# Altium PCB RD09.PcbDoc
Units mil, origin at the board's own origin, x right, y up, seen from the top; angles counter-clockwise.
Board outline 1064.96 x 551.18 mil, 4 copper layers (Top Layer, Mid Layer 1, Mid Layer 2, Bottom Layer), stack 56.756 mil thick; 39 components, 35 nets, 118 pads, 211 vias.
Unrouted connection lines stored in the file: 34.
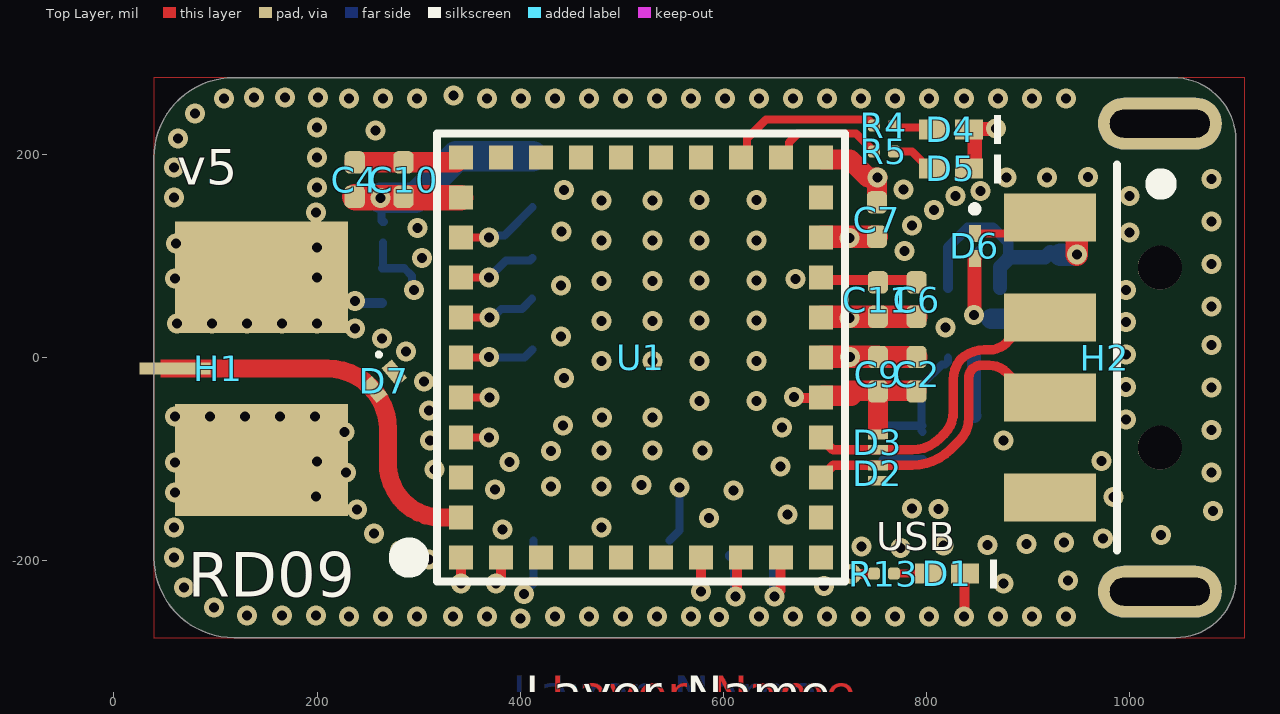
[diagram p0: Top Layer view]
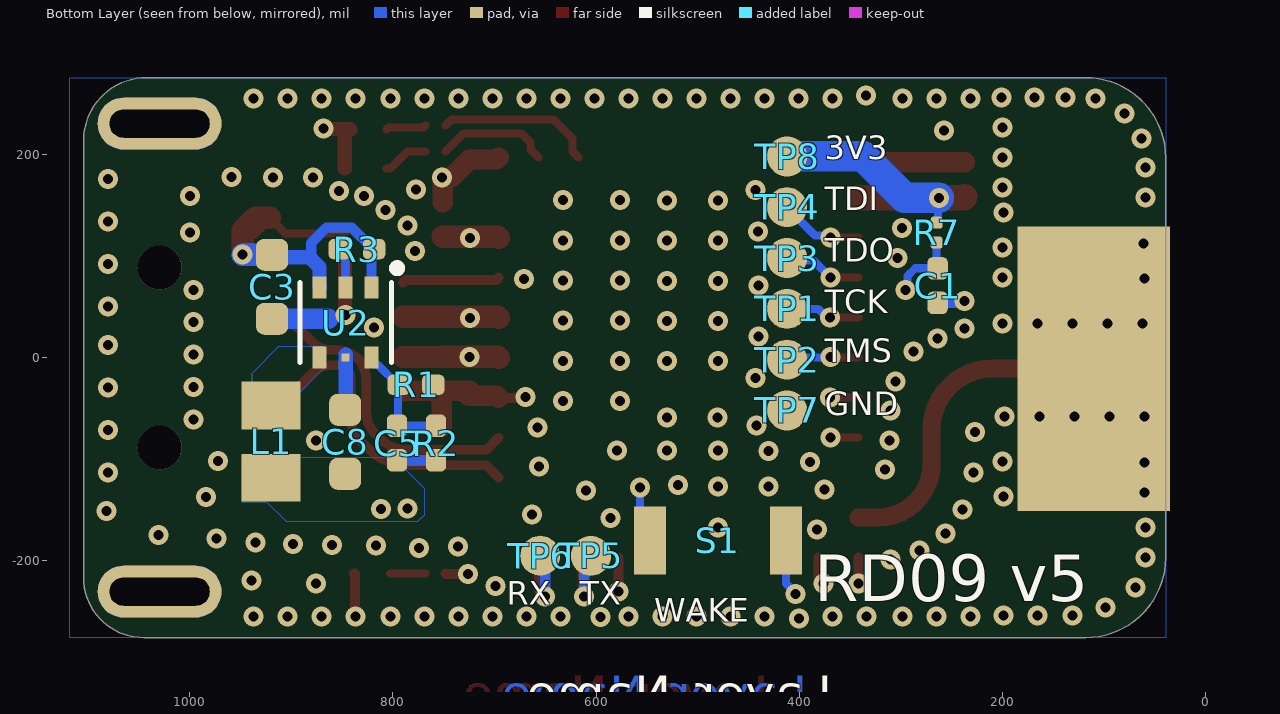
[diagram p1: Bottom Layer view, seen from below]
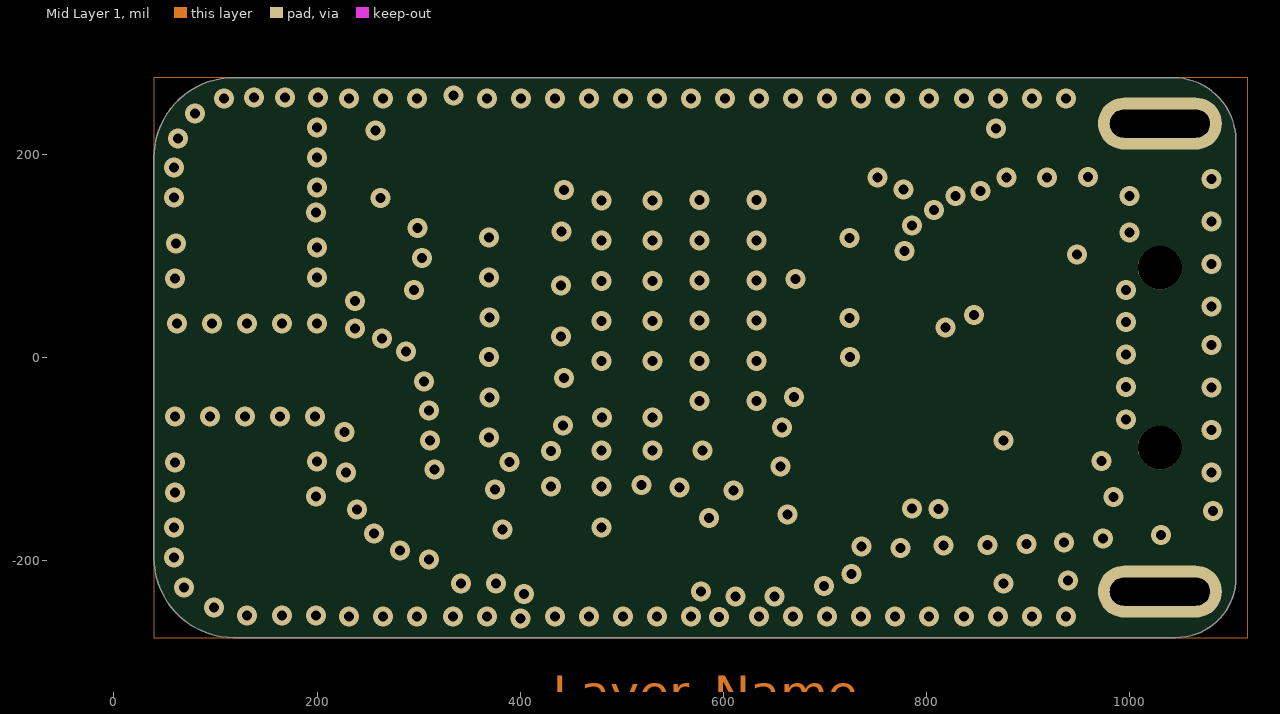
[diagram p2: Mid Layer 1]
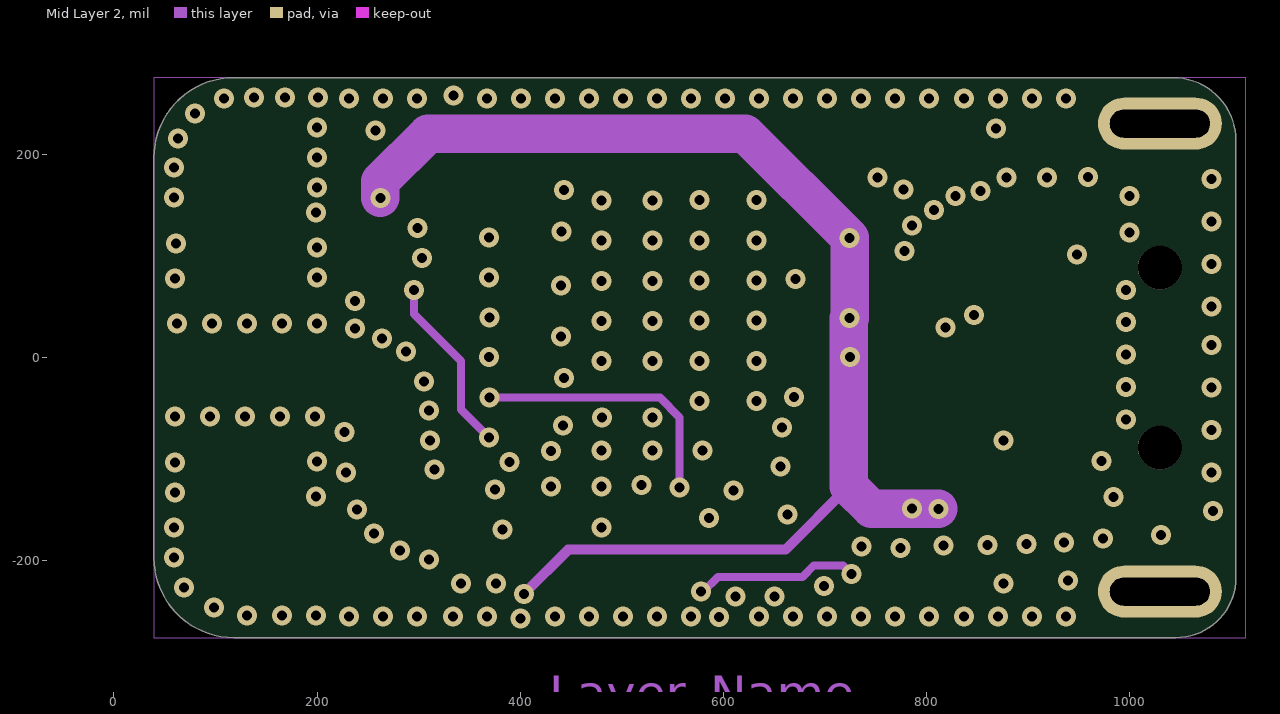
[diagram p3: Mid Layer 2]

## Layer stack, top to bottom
Top Solder: solder mask 0.787, SM-001, Dk 4.2
Top Layer: signal copper 1.378
Dielectric 1: prepreg 12, PP, Dk 4.29
Mid Layer 1: signal copper 1.378
Dielectric 2: core 27.2441, Core, Dk 4.29
Mid Layer 2: signal copper 1.378
Dielectric 3: prepreg 12, PP, Dk 4.29
Bottom Layer: signal copper 1.378
Bottom Solder: solder mask 0.787, SM-001, Dk 4.2

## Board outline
39.37,-196.85 39.37,196.85 cw(c118.11,196.85) 118.11,275.59 1042.32,275.59 cw(c1042.32,213.58) 1104.33,213.58 1104.33,-216.54 cw(c1045.28,-216.54) 1045.28,-275.59 118.11,-275.59 cw(c118.11,-196.85)

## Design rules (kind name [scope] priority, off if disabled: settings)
AssemblyTestPointUsage [All] p0: scope1count=1 scope1_0_kind=Board scope1_0_value=Board scope2count=1 scope2_0_kind=Board scope2_0_value=Board commentlength=0
AssemblyTestpoint [All] p0: scope1count=1 scope1_0_kind=Board scope1_0_value=Board scope2count=1 scope2_0_kind=Board scope2_0_value=Board commentlength=0
BoardOutlineClearance [All] p0: scope1count=1 scope1_0_kind=Board scope1_0_value=Board scope2count=1 scope2_0_kind=Board scope2_0_value=Board commentlength=0 gap=6
BoardOutlineClearance [All] p1: gap=6 ignorepadtopadclearanceinfootprint=FALSE
Clearance [All] p0 off: scope1count=1 scope1_0_kind=Board scope1_0_value=Board scope2count=1 scope2_0_kind=Board scope2_0_value=Board commentlength=69 gap=5 // Protel DXP Scope 2 Expression Was: Not(OnLayer('Keep-Out Layer'))
Clearance "Poly Clearance" [All] p0 off: scope1count=1 scope1_0_kind=Board scope1_0_value=Board scope2count=1 scope2_0_kind=Board scope2_0_value=Board commentlength=50 gap=4 // Protel DXP Scope 1 Expression Was: (InPolygon)
Clearance "Poly Clearance_USB" [All] p0 off: scope1count=1 scope1_0_kind=Board scope1_0_value=Board scope2count=1 scope2_0_kind=Board scope2_0_value=Board commentlength=50 gap=5.74 // Protel DXP Scope 2 Expression Was: (InPolygon)
Clearance Clearance_RF [All] p0 off: scope1count=1 scope1_0_kind=Board scope1_0_value=Board scope2count=1 scope2_0_kind=Board scope2_0_value=Board commentlength=50 gap=11.81 // Protel DXP Scope 2 Expression Was: (InPolygon)
Clearance Clearance_keepout [All] p0 off: scope1count=1 scope1_0_kind=Layer scope1_0_value=TOP scope2count=1 scope2_0_kind=Board scope2_0_value=Board commentlength=50 gap=6 // Protel DXP Scope 2 Expression Was: (InPolygon)
Clearance Clearance_RFVia [All] p0 off: scope1count=1 scope1_0_kind=Board scope1_0_value=Board scope2count=1 scope2_0_kind=Board scope2_0_value=Board commentlength=71 gap=7 // Protel DXP Scope 1 Expression Was: (IsVia AND InNetClass('RF-Net'))
Clearance Clearance_RFVia [(IsVia AND InNetClass('RF-Net'))] p1: gap=7 ignorepadtopadclearanceinfootprint=FALSE
Clearance Clearance_keepout [OnLayer('Keep-Out Layer') vs (InPolygon)] p2: gap=6 ignorepadtopadclearanceinfootprint=FALSE except(0: Arc-Hole Track-Hole SMDPad-Hole THPad-Hole Via-Hole Fill-Hole Poly-Hole Region-Hole Text-Hole)
Clearance Clearance_RF [InNetClass('RF-Net') and ( IsArc or IsTrack ) vs (InPolygon)] p3: gap=11.81 ignorepadtopadclearanceinfootprint=FALSE
Clearance "Poly Clearance_USB" [InNet('USB_D_N') or InNet('USB_D_P') vs (InPolygon)] p4: gap=5.74 ignorepadtopadclearanceinfootprint=FALSE
Clearance "Poly Clearance" [(InPolygon)] p5: gap=4 ignorepadtopadclearanceinfootprint=FALSE except(0: Arc-Hole Track-Hole SMDPad-Hole THPad-Hole Via-Hole Fill-Hole Poly-Hole Region-Hole Text-Hole)
Clearance [Not(OnLayer('Keep-Out Layer')) vs Not(OnLayer('Keep-Out Layer'))] p6: gap=5 ignorepadtopadclearanceinfootprint=FALSE
ComponentClearance COMP_OTHER-COMP_OTHER [All] p0: scope1count=1 scope1_0_kind=ComponentClass scope1_0_value=COMP_OTHER scope2count=1 scope2_0_kind=ComponentClass scope2_0_value=COMP_OTHER commentlength=0 gap=14.96 collisioncheckmode=3
ComponentClearance CHIP_MICRO-COMP_OTHER [All] p0: scope1count=1 scope1_0_kind=ComponentClass scope1_0_value=CHIP_MICRO scope2count=1 scope2_0_kind=ComponentClass scope2_0_value=COMP_OTHER commentlength=0 gap=11.81 collisioncheckmode=3
ComponentClearance COMP_BGA-COMP_OTHER [All] p0: scope1count=1 scope1_0_kind=ComponentClass scope1_0_value=COMP_BGA scope2count=1 scope2_0_kind=ComponentClass scope2_0_value=COMP_OTHER commentlength=0 gap=23.62 collisioncheckmode=3
ComponentClearance COMP_BGA-COMP_BGA [All] p0: scope1count=1 scope1_0_kind=ComponentClass scope1_0_value=COMP_BGA scope2count=1 scope2_0_kind=ComponentClass scope2_0_value=COMP_BGA commentlength=0 gap=39.37 collisioncheckmode=3
ComponentClearance CHIP_MICRO-COMP_BGA [All] p0: scope1count=1 scope1_0_kind=ComponentClass scope1_0_value=CHIP_MICRO scope2count=1 scope2_0_kind=ComponentClass scope2_0_value=COMP_BGA commentlength=0 gap=11.81 collisioncheckmode=3
ComponentClearance CHIP_OTHER-COMP_OTHER [All] p0: scope1count=1 scope1_0_kind=ComponentClass scope1_0_value=CHIP_OTHER scope2count=1 scope2_0_kind=ComponentClass scope2_0_value=COMP_OTHER commentlength=0 gap=14.96 collisioncheckmode=3
ComponentClearance CHIP_OTHER-COMP_BGA [All] p0: scope1count=1 scope1_0_kind=ComponentClass scope1_0_value=CHIP_OTHER scope2count=1 scope2_0_kind=ComponentClass scope2_0_value=COMP_BGA commentlength=0 gap=14.96 collisioncheckmode=3
ComponentClearance CHIP_OTHER-CHIP_OTHER [All] p0: scope1count=1 scope1_0_kind=ComponentClass scope1_0_value=CHIP_OTHER scope2count=1 scope2_0_kind=ComponentClass scope2_0_value=CHIP_OTHER commentlength=0 gap=9.84 collisioncheckmode=3
ComponentClearance CHIP_MICRO-CHIP_OTHER [All] p0: scope1count=1 scope1_0_kind=ComponentClass scope1_0_value=CHIP_MICRO scope2count=1 scope2_0_kind=ComponentClass scope2_0_value=CHIP_OTHER commentlength=0 gap=9.84 collisioncheckmode=3
ComponentClearance CHIP_MICRO-CHIP_MICRO [All] p0: scope1count=1 scope1_0_kind=ComponentClass scope1_0_value=CHIP_MICRO scope2count=1 scope2_0_kind=ComponentClass scope2_0_value=CHIP_MICRO commentlength=0 gap=7.87 collisioncheckmode=3
ComponentClearance [All] p0: scope1count=1 scope1_0_kind=Component scope1_0_value=SHIELD scope2count=1 scope2_0_kind=Board scope2_0_value=Board commentlength=0 gap=11.81 collisioncheckmode=3
ComponentClearance [InComponent('SHIELD')] p1: gap=11.81 collisioncheckmode=3 verticalgap=10 showdistances=FALSE
ComponentClearance CHIP_MICRO-CHIP_MICRO [InComponentClass('CHIP_MICRO') vs InComponentClass('CHIP_MICRO')] p2: gap=7.87 collisioncheckmode=3 verticalgap=3.94 showdistances=TRUE
ComponentClearance CHIP_MICRO-CHIP_OTHER [InComponentClass('CHIP_MICRO') vs InComponentClass('CHIP_OTHER')] p3: gap=9.84 collisioncheckmode=3 verticalgap=3.94 showdistances=TRUE
ComponentClearance CHIP_OTHER-CHIP_OTHER [InComponentClass('CHIP_OTHER') vs InComponentClass('CHIP_OTHER')] p4: gap=9.84 collisioncheckmode=3 verticalgap=3.94 showdistances=TRUE
ComponentClearance CHIP_OTHER-COMP_BGA [InComponentClass('CHIP_OTHER') vs InComponentClass('COMP_BGA')] p5: gap=14.96 collisioncheckmode=3 verticalgap=3.94 showdistances=TRUE
ComponentClearance CHIP_OTHER-COMP_OTHER [InComponentClass('CHIP_OTHER') vs InComponentClass('COMP_OTHER')] p6: gap=14.96 collisioncheckmode=3 verticalgap=3.94 showdistances=TRUE
ComponentClearance CHIP_MICRO-COMP_BGA [InComponentClass('CHIP_MICRO') vs InComponentClass('COMP_BGA')] p7: gap=11.81 collisioncheckmode=3 verticalgap=3.94 showdistances=TRUE
ComponentClearance COMP_BGA-COMP_BGA [InComponentClass('COMP_BGA') vs InComponentClass('COMP_BGA')] p8: gap=39.37 collisioncheckmode=3 verticalgap=3.94 showdistances=TRUE
ComponentClearance COMP_BGA-COMP_OTHER [InComponentClass('COMP_BGA') vs InComponentClass('COMP_OTHER')] p9: gap=23.62 collisioncheckmode=3 verticalgap=3.94 showdistances=TRUE
ComponentClearance CHIP_MICRO-COMP_OTHER [InComponentClass('CHIP_MICRO') vs InComponentClass('COMP_OTHER')] p10: gap=11.81 collisioncheckmode=3 verticalgap=3.94 showdistances=TRUE
ComponentClearance COMP_OTHER-COMP_OTHER [InComponentClass('COMP_OTHER') vs InComponentClass('COMP_OTHER')] p11: gap=14.96 collisioncheckmode=3 verticalgap=3.94 showdistances=TRUE
DiffPairsRouting [All] p0: scope1count=1 scope1_0_kind=Board scope1_0_value=Board scope2count=1 scope2_0_kind=Board scope2_0_value=Board commentlength=0
DiffPairsRouting [All] p1: maxlimit=10 minlimit=5 mostfreqgap=10 toplayer_mingap=5.74 toplayer_maxgap=5.74 toplayer_prefgap=5.74 toplayer_minwidth=9.45 toplayer_maxwidth=9.45 toplayer_prefwidth=9.45 impedanceprofiledriven=TRUE impedanceprofileid={6CDD10DD-8A0B-4EE0-BC50-81CF0CD2B6CE} impedanceprofilevalue=90.000000 maxuncoupledlength=500
FabricationTestPointUsage TestPointUsage [All] p0: scope1count=1 scope1_0_kind=Board scope1_0_value=Board scope2count=1 scope2_0_kind=Board scope2_0_value=Board commentlength=0 valid=0 allowmultiple=FALSE
FabricationTestPointUsage TestPointUsage [All] p1: valid=0 allowmultiple=FALSE
FabricationTestpoint Testpoint [All] p0: scope1count=1 scope1_0_kind=Board scope1_0_value=Board scope2count=1 scope2_0_kind=Board scope2_0_value=Board commentlength=0 side=3 testpointundercomponent=TRUE minsize=40 maxsize=100 preferedsize=60 minholesize=0 maxholesize=40 preferedholesize=32 testpointgrid=1
FabricationTestpoint Testpoint [All] p1: side=3 testpointundercomponent=TRUE minsize=40 maxsize=100 preferedsize=60 minholesize=0 maxholesize=40 preferedholesize=32 testpointgrid=1 allowsidetop=TRUE allowsidebottom=TRUE usegrid=TRUE gridtolerance=0.01
FanoutControl Fanout_Default [All] p0: scope1count=1 scope1_0_kind=Board scope1_0_value=Board scope2count=1 scope2_0_kind=Board scope2_0_value=Board commentlength=30 // Fanout_Default (Default Rule)
FanoutControl Fanout_Small [All] p0 off: scope1count=1 scope1_0_kind=Board scope1_0_value=Board scope2count=1 scope2_0_kind=Board scope2_0_value=Board commentlength=84 // Protel DXP Scope 1 Expression Was: (CompPinCount < 5)   Fanout_Small (Default Rule)
FanoutControl Fanout_SOIC [All] p0 off: scope1count=1 scope1_0_kind=Board scope1_0_value=Board scope2count=1 scope2_0_kind=Board scope2_0_value=Board commentlength=71 // Protel DXP Scope 1 Expression Was: IsSOIC   Fanout_SOIC (Default Rule)
FanoutControl Fanout_LCC [All] p0 off: scope1count=1 scope1_0_kind=Board scope1_0_value=Board scope2count=1 scope2_0_kind=Board scope2_0_value=Board commentlength=69 // Protel DXP Scope 1 Expression Was: IsLCC   Fanout_LCC (Default Rule)
FanoutControl Fanout_BGA [All] p0 off: scope1count=1 scope1_0_kind=Board scope1_0_value=Board scope2count=1 scope2_0_kind=Board scope2_0_value=Board commentlength=69 // Protel DXP Scope 1 Expression Was: IsBGA   Fanout_BGA (Default Rule)
Height [All] p0: scope1count=1 scope1_0_kind=Board scope1_0_value=Board scope2count=1 scope2_0_kind=Board scope2_0_value=Board commentlength=0
HoleSize [All] p0 off: scope1count=1 scope1_0_kind=Board scope1_0_value=Board scope2count=1 scope2_0_kind=Board scope2_0_value=Board commentlength=0 absolutevalues=TRUE maxlimit=100 minlimit=5.91 maxpercent=80.000 minpercent=20.000
HoleSize [All] p1 off: absolutevalues=TRUE maxlimit=100 minlimit=5.91 maxpercent=80.000 minpercent=20.000
HoleToHoleClearance [All] p0: scope1count=1 scope1_0_kind=Board scope1_0_value=Board scope2count=1 scope2_0_kind=Board scope2_0_value=Board commentlength=0
HoleToHoleClearance [All] p1: gap=8 allowstackedmicrovias=TRUE
LayerPairs [All] p0: scope1count=1 scope1_0_kind=Board scope1_0_value=Board scope2count=1 scope2_0_kind=Board scope2_0_value=Board commentlength=0 enforce=TRUE
MaxMinImpedance [All] p0: scope1count=1 scope1_0_kind=Board scope1_0_value=Board scope2count=1 scope2_0_kind=Board scope2_0_value=Board commentlength=0 minimum=1.000 maximum=10.00
MaxMinImpedance [All] p1: minimum=1.000 maximum=10.00
MinimumAnnularRing [All] p0: scope1count=1 scope1_0_kind=Board scope1_0_value=Board scope2count=1 scope2_0_kind=Board scope2_0_value=Board commentlength=0 minimumring=2.52
MinimumAnnularRing [All] p1: minimumring=2.52
MinimumSolderMaskSliver [All] p0: scope1count=1 scope1_0_kind=Board scope1_0_value=Board scope2count=1 scope2_0_kind=Board scope2_0_value=Board commentlength=0
MinimumSolderMaskSliver [All] p1: minsoldermaskwidth=5
NetAntennae [All] p0: scope1count=1 scope1_0_kind=Board scope1_0_value=Board scope2count=1 scope2_0_kind=Board scope2_0_value=Board commentlength=0
PasteMaskExpansion [All] p0: scope1count=1 scope1_0_kind=Board scope1_0_value=Board scope2count=1 scope2_0_kind=Board scope2_0_value=Board commentlength=0 expansion=0
PlaneClearance [All] p0: scope1count=1 scope1_0_kind=Board scope1_0_value=Board scope2count=1 scope2_0_kind=Board scope2_0_value=Board commentlength=0 clearance=5
PlaneClearance [All] p1: clearance=5
PlaneConnect [All] p0: scope1count=1 scope1_0_kind=Board scope1_0_value=Board scope2count=1 scope2_0_kind=Board scope2_0_value=Board commentlength=0 planeconnectstyle=Direct reliefexpansion=19.68 reliefentries=4 reliefconductorwidth=7.87 reliefairgap=7.87
PlaneConnect [All] p1: planeconnectstyle=Direct reliefexpansion=19.68 reliefentries=4 reliefconductorwidth=7.87 reliefairgap=7.87
PolygonConnect [All] p0: scope1count=1 scope1_0_kind=Board scope1_0_value=Board scope2count=1 scope2_0_kind=Board scope2_0_value=Board commentlength=0 connectstyle=Relief reliefconductorwidth=10 reliefentries=4 polygonreliefangle="90 Angle"
PolygonConnect [All] p1: thpad.connectstyle=Relief thpad.reliefconductorwidth=10 thpad.reliefentries=4 thpad.polygonreliefangle="90 Angle" thpad.airgapwidth=10 smdpad.connectstyle=Direct smdpad.reliefconductorwidth=10 smdpad.reliefentries=4 smdpad.polygonreliefangle="90 Angle" smdpad.airgapwidth=10 via.connectstyle=Direct via.reliefconductorwidth=10 via.reliefentries=4 via.polygonreliefangle="90 Angle" via.airgapwidth=10
RoutingCorners [All] p0: scope1count=1 scope1_0_kind=Board scope1_0_value=Board scope2count=1 scope2_0_kind=Board scope2_0_value=Board commentlength=0 cornerstyle=45-Degree minsetback=100 maxsetback=100
RoutingLayers [All] p0: scope1count=1 scope1_0_kind=Board scope1_0_value=Board scope2count=1 scope2_0_kind=Board scope2_0_value=Board commentlength=0 top layer=Automatic mid layer 1=Automatic mid layer 3=Automatic bottom layer=Automatic
RoutingPriority [All] p0: scope1count=1 scope1_0_kind=Board scope1_0_value=Board scope2count=1 scope2_0_kind=Board scope2_0_value=Board commentlength=0
RoutingTopology [All] p0: scope1count=1 scope1_0_kind=Board scope1_0_value=Board scope2count=1 scope2_0_kind=Board scope2_0_value=Board commentlength=0 topology=Shortest
RoutingVias [All] p0 off: scope1count=1 scope1_0_kind=Board scope1_0_value=Board scope2count=1 scope2_0_kind=Board scope2_0_value=Board commentlength=98 holewidth=7.87 width=19.68 viastyle="Through Hole" minholewidth=7.87 minwidth=17.72 maxholewidth=39.37 maxwidth=78.74 // Protel DXP Scope 1 Expression Was: (StartLayer = 'Top Layer') and (StopLayer = 'Bottom Layer')
RoutingVias [(StartLayer = 'Top Layer') and (StopLayer = 'Bottom Layer')] p1: holewidth=7.87 width=19.68 viastyle="Through Hole" minholewidth=7.87 minwidth=17.72 maxholewidth=39.37 maxwidth=78.74 useviatemplates=TRUE viatemplateguid#1={677E590D-0BF1-4610-8777-1DBFB77D696D} viatemplateguid#2={CDA64F6E-BB79-405B-BF2A-9310D52A7923} viatemplatename#1=v50h25m0mx0 viatemplatename#2=v30h15m0mx0(1)
ShortCircuit [All] p0: scope1count=1 scope1_0_kind=Board scope1_0_value=Board scope2count=1 scope2_0_kind=Board scope2_0_value=Board commentlength=0 allowed=FALSE
SilkToBoardRegionClearance [All] p0: scope1count=1 scope1_0_kind=Board scope1_0_value=Board scope2count=1 scope2_0_kind=Board scope2_0_value=Board commentlength=0
SilkToSilkClearance [All] p0: scope1count=1 scope1_0_kind=Board scope1_0_value=Board scope2count=1 scope2_0_kind=Board scope2_0_value=Board commentlength=0
SilkToSolderMaskClearance SilkscreenOverComponentPads [All] p0 off: scope1count=1 scope1_0_kind=Board scope1_0_value=Board scope2count=1 scope2_0_kind=Board scope2_0_value=Board commentlength=44 // Protel DXP Scope 1 Expression Was: IsPad
SilkToSolderMaskClearance SilkscreenOverComponentPads [IsPad] p1: minsilkscreentomaskgap=7.7 clearancetoexposedcopper=TRUE
SolderMaskExpansion [All] p0: scope1count=1 scope1_0_kind=Board scope1_0_value=Board scope2count=1 scope2_0_kind=Board scope2_0_value=Board commentlength=0 expansion=4
SolderMaskExpansion [All] p1: expansion=4 istentingtop=FALSE
SupplyNets "Schematic Supply Nets_2" [All] p0: scope1count=1 scope1_0_kind=Net scope1_0_value=VDD_3V3 scope2count=1 scope2_0_kind=Board scope2_0_value=Board commentlength=0 voltage=0.000
SupplyNets "Schematic Supply Nets_1" [All] p0: scope1count=1 scope1_0_kind=Net scope1_0_value=GND scope2count=1 scope2_0_kind=Board scope2_0_value=Board commentlength=0 voltage=0.000
SupplyNets "Schematic Supply Nets" [All] p0: scope1count=1 scope1_0_kind=Net scope1_0_value=5V_USB scope2count=1 scope2_0_kind=Board scope2_0_value=Board commentlength=0 voltage=0.000
SupplyNets "Schematic Supply Nets_2" [InNet('VDD_3V3')] p1: voltage=0.000
SupplyNets "Schematic Supply Nets_1" [InNet('GND')] p2: voltage=0.000
SupplyNets "Schematic Supply Nets" [InNet('5V_USB')] p3: voltage=0.000
UnRoutedNet [All] p0: scope1count=1 scope1_0_kind=Board scope1_0_value=Board scope2count=1 scope2_0_kind=Board scope2_0_value=Board commentlength=0
UnpouredPolygon [All] p0: scope1count=1 scope1_0_kind=Board scope1_0_value=Board scope2count=1 scope2_0_kind=Board scope2_0_value=Board commentlength=0
Width [All] p0: scope1count=1 scope1_0_kind=Board scope1_0_value=Board scope2count=1 scope2_0_kind=Board scope2_0_value=Board commentlength=0 maxlimit=100 minlimit=5 preferedwidth=8
Width "RF Net width" [All] p0 off: scope1count=1 scope1_0_kind=Board scope1_0_value=Board scope2count=1 scope2_0_kind=Board scope2_0_value=Board commentlength=61 maxlimit=20 minlimit=3.95 preferedwidth=19.85 // Protel DXP Scope 1 Expression Was: (InNetClass('RF-Net'))
Width "RF Net width" [(InNetClass('RF-Net'))] p1: maxlimit=20 minlimit=3.95 preferedwidth=19.85 toplayer_minwidth=7 toplayer_prefwidth=17.87 impedanceprofiledriven=TRUE impedanceprofileid={2BAD1660-FF1E-4629-AB45-93BC2CD73358} impedanceprofilevalue=50.000000 minimp=50.000000 maximp=50.000000 favimp=50.000000
Width [All] p2: maxlimit=100 minlimit=5 preferedwidth=8 minimp=50.000000 maximp=50.000000 favimp=50.000000
20 further rules are at their usual default settings.

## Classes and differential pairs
component class PCB_PATTERN: TP1 TP2 TP3 TP4 TP5 TP6 TP7 TP8
net class RF-Net: NetD7_2
component class CHIP_OTHER: C3 C8 D1 D4 D5 L1
component class CHIP_MICRO: C1 C2 C4 C5 C6 C7 C9 C10 C11 D6 R1 R3 R4 R5 R7 R13
component class COMP_OTHER: H1 H2 S1 U1 U2
differential pair " ": +USB_D_P -USB_D_N

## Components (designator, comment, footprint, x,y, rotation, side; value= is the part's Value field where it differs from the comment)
C1 "GRM155R61E225ME15D" 0402_cap_rnd#1 263.78,70.9 r270 bottom
C2 "CL05A106MP5NUNC" 0402_cap_rnd#1 790,-16.41 r270 top
C3 "GRM188R61E106MA73J" 0603_cap_rnd 918.79,69.72 r270 bottom
C4 "CL05A106MP5NUNC" 0402_cap_rnd#1 237.01,175.2 r90 top
C5 "CGA2B2NP01H220J050BA" 0402_cap 795.84,-84.07 r90 bottom
C6 "CL05A106MP5NUNC" 0402_cap_rnd#1 790,57.09 r90 top
C7 "C0402C104K8RACTU" 0402_cap_rnd#2 750.98,135.83 r90 top
C8 "GRM188R61E106MA73J" 0603_cap_rnd 846.83,-82.82 r90 bottom
C9 "C0402C104K8RACTU" 0402_cap_rnd#2 751.97,-16.41 r270 top
C10 "C0402C104K8RACTU" 0402_cap_rnd#2 285.04,175.2 r90 top
C11 "C0402C104K8RACTU" 0402_cap_rnd#2 751.97,57.09 r90 top
D1 "XZVGR68W-3" LED_0402_GREEN 820.21,-212.6 r0 top
D2 "SP3522-01UTG" SP3522-01ETG-Footprint-1 751.97,-113.69 r180 top
D3 "SP3522-01UTG" SP3522-01ETG-Footprint-1 751.97,-83.13 r0 top
D4 "LED_R" LED_0402_RED 823.82,224.41 r0 top
D5 "LED_G" LED_0402_GREEN 823.82,186.02 r0 top
D6 "ESDALC6V1-1U2" 0201_DIODE 847.34,109.95 r270 top
D7 "ESD103B102ELE6327XTMA1" INF-TSLP-2-20_V 266.09,-23.32 r310 top
H1 "142-0761-861" SMA_EMERSON_142_0761_861 35.16,-10.83 r90 top locked
H2 "USBA" USBA_BOARD_INLINE 1029.53,0 r90 top locked
L1 "LQM21PN2R2MGHL" INDC2112X06N 919.88,-82.8 r270 bottom
R1 "RC0402FR-07100KL" 0402_res_rnd 777.09,-26.72 r180 bottom
R2 "CRCW0402453KFKEDC" 0402_res 757.51,-84.07 r90 bottom
R3 "RC0402FR-07100KL" 0402_res_rnd 835.39,106.78 r0 bottom
R4 "RES" 0201_res_rnd 757.87,228.35 r0 top
R5 "RES" 0201_res_rnd 757.87,202.76 r0 top
R7 "RC0201FR-07220KL" 0201_res_rnd 264.76,123 r90 bottom
R13 "RC0201FR-07330RL" 0201_res_rnd 757.87,-212.6 r0 top
S1 "B3U-1000P" B3U-1000P 480,-180 r180 bottom
TP1 "PAD0035" TP_40_SMT#1 392.72,38.39 r90 bottom
TP2 "PAD0035" TP_40_SMT#2 392.72,0 r90 bottom
TP3 "PAD0035" TP_40_SMT#3 392.72,78.74 r90 bottom
TP4 "PAD0035" TP_40_SMT#4 392.72,118.11 r90 bottom
TP5 "PAD0035" TP_40_SMT#5 605,-195.04 r90 bottom
TP6 "PAD0035" TP_40_SMT#5 655,-195 r90 bottom
TP7 "PAD0035" TP_40_SMT#6 1178.07,-206.93 r90 bottom
TP8 "PAD0035" TP_40_SMT#7 1408.39,-206.93 r90 bottom
U1 "MM8108-MF15" MF15 341.54,-196.84 r90 top locked
U2 "AP3401DNTR-G1" AP3401DNTR-G1-Footprint-1 891.4,44.35 r270 bottom

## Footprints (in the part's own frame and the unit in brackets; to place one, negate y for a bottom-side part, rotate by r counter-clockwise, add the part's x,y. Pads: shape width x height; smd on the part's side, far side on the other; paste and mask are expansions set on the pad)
0201_DIODE [mm]
  rect 0.425x0.3 smd mask+0: A(0.31,0) K(-0.31,0)
0201_res_rnd [mm]
  rrect50% 0.3x0.3 smd mask+0: 1(-0.25,0) 2(0.25,0)
0402_cap [mil]
  rrect50% 22x20 smd: 1(-17,0) 2(17,0)
0402_cap_rnd#1 [mil]
  rrect50% 22x20 smd mask+0: 1(-17,0) 2(17,0)
0402_cap_rnd#2 [mil]
  rrect50% 22x20 smd: 1(-17,0) 2(17,0)
0402_res [mil]
  rrect50% 22x20 smd: 1(-17,0) 2(17,0)
0402_res_rnd [mil]
  rrect50% 22x20 smd mask+0: 1(-17,0) 2(17,0)
0603_cap_rnd [mm]
  rrect50% 0.8x0.8 smd mask+0: 1(-0.8,0) 2(0.8,0)
AP3401DNTR-G1-Footprint-1 [mm]
  rect 0.55x0.35 smd mask+0: 1(-0.621,1.793) 2(-0.621,1.143) 3(-0.621,0.493) 4(1.129,0.493) 6(1.129,1.793)
  rect 0.2x0.2 smd paste-1 mask+0: 5(1.129,1.143)
  silkscreen extent -1.21,0 1.25,2.53
B3U-1000P [mm]
  rect 0.8x1.7 smd: 1(-1.7,0) 2(1.7,0)
INDC2112X06N [mm] "Chip Inductor, 2-Leads, Body 2.10x1.25mm, IPC Medium Density"
  rect 1.19x1.47 smd: 1(-0.905,0) 2(0.905,0)
INF-TSLP-2-20_V [mm] "TSLP, 2-Leads, Body 1x0.6mm, Pitch 0.65mm"
  rect 0.6x0.35 smd: 1(0,0.325) 2(0,-0.325)
  silkscreen extent -0.65,0.28 -0.55,0.37
LED_0402_GREEN [mm]
  rect 0.7x0.5 smd: A(-0.45,0) K(0.45,0)
  silkscreen extent 1.07,-0.37 1.24,0.36
LED_0402_RED [mm]
  rect 0.7x0.5 smd: A(-0.45,0) K(0.45,0)
  silkscreen extent 1.08,-0.36 1.26,0.36
MF15 [mm]
  rect 0.6x0.6 smd: 1(0,0) 2(1,0) 3(2,0) 4(3,0) 5(4,0) 6(5,0) 7(6,0) 8(7,0) 9(8,0) 10(9,0) 11(10,0) 12(10,-1) 13(10,-2) 14(10,-3) 15(10,-4) 16(10,-5) 17(10,-6) 18(10,-7) 19(10,-8) 20(10,-9) 21(9,-9) 22(8,-9) 23(7,-9) 24(6,-9) 25(5,-9) 26(4,-9) 27(3,-9) 28(2,-9) 29(1,-9) 30(0,-9) 31(0,-8) 32(0,-7) 33(0,-6) 34(0,-5) 35(0,-4) 36(0,-3) 37(0,-2) 38(0,-1)
  silkscreen extent -0.6,-9.6 10.6,1.55
SMA_EMERSON_142_0761_861 [mil]
  rect 11.81x70 smd mask+0: 1(0,-25)
  rect 110x170 smd mask+0: 2(-90,-110) 2(90,-110)
  rect 280x150 smd far side: 2(0,-75)
SP3522-01ETG-Footprint-1 [mm]
  rect 0.5x0.24 smd mask+0: A(0,0.19) K(0,-0.19)
TP_40_SMT#1 [mm]
  round 1 smd: 1(0.244,0.49)
TP_40_SMT#2 [mm]
  round 1 smd: 1(-0.051,0.49)
TP_40_SMT#3 [mm]
  round 1 smd: 1(0.489,0.49)
TP_40_SMT#4 [mm]
  round 1 smd: 1(0.759,0.49)
TP_40_SMT#5 [mm]
  round 1 smd: 1(0,0)
TP_40_SMT#6 [mm]
  round 1 smd: 1(3.935,-19.458)
TP_40_SMT#7 [mm]
  round 1 smd: 1(10.285,-25.308)
USBA_BOARD_INLINE [mm]
  rect 1.2x2.3 smd: 1(3.5,2.75) 2(1,2.75) 3(-1,2.75) 4(-3.5,2.75)
  oval 1.3x3.1 hole 0.7 slot 2.5 at 90 deg: 5(-5.85,0) 6(5.85,0)
  round 1.1 hole 1.1 unplated: ""(-2.25,0) ""(2.25,0)
  Bottom Layer lines w0.3: -5.85,1.4 cw(c-5.85,0.9) -5.35,0.9 -5.35,-0.9 cw(c-5.85,-0.9) -5.85,-1.4 cw(c-5.85,-0.9) -6.35,-0.9 -6.35,0.9 cw(c-5.85,0.9) -5.85,1.4 ; 5.85,1.4 cw(c5.85,0.9) 6.35,0.9 6.35,-0.9 cw(c5.85,-0.9) 5.85,-1.4 cw(c5.85,-0.9) 5.35,-0.9 5.35,0.9 cw(c5.85,0.9) 5.85,1.4
  silkscreen extent -4.83,-0.22 4.83,1.07

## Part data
C1: library part CAP0055-14, "CAP CER 2.2UF 25V ±20% X5R 0402"
C2 C4 C6: library part CAP0268-1, "Ceramic Capacitor, Multilayer, Ceramic, 10V, 20% +Tol, 20% -Tol, X5R, 15% TC, 10uF, Surface Mount, 0402"
C3 C8: library part CAP0197-10, "CAP CER 10UF 25V ±20% X5R 0603"
C5: library part CAP0017-14, "CAP CER 22PF 50V ±5% C0G/NP0 0402"
C7 C9 C10 C11: library part CAP0025-15, "CAP CER 100NF 10V ±10% X7R 0402"
D1 D5: library part DIO0053-7, "LED GREEN 0402 SMD"
D2 D3: library part DIO0091-2, "ESD protection diodes / TVS diodes; LITTELFUSE; SP3522-01UTG; Surface Mount 0201"
D4: library part DIO0052-9, "LED RED 0402 SMD"
D6: library part DIO0043-5, "TVS DIODE 3VWM ST020"
D7: library part DIO0089-8, "ESD103B102 Series 1 Line 15 V 0.2pF Bi-Direction TVS Protection Device-TSLP-2-20"
H1: library part JCK0001-4, "Conn, SMA Jack 50 Ohm PCB Edge Mount Gold, RoHS"
H2: library part PLG0003-1, "USB Connector, 4 Contact(s), Male, Right Angle, Surface Mount Terminal, Locking"
L1: library part IND0084-2, "FIXED IND 2.2uH 1.3A 156 MOHM 0805 ±20%"
R1 R3: library part RES0044-14, "RES SMD 100K OHM ±1% 1/16W 0402"
R2: library part CMP-00022-3, "Fixed Resistor, Metal Glaze/thick Film, 0.063W, 453000ohm, 50V, 1% +/-Tol, 100ppm/Cel, Surface Mount, 0402"
R4 R5 R13: library part RES0020-12, "RES SMD 330R OHM ±1% 1/20W 0201"
R7: library part RES0314-1, "RES SMD 220K OHM ±1% 1/20W 0201"
S1: library part SWH0022-1, "SWITCH TACTILE SPST-NO 0.05A 12V"
TP1 TP2 TP3 TP4 TP5 TP6 TP7 TP8: library part PAD0035-2, "40mil 1mm SMD Test Point"
U1: library part MOD0024-12
U2: library part CMP-00018-3, "Switching Regulator, Current-mode, 1500kHz Switching Freq-Max, PDSO6"

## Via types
v1: diameter 19.68, hole 9.84, Top Layer to Bottom Layer, tented both sides, 211 vias

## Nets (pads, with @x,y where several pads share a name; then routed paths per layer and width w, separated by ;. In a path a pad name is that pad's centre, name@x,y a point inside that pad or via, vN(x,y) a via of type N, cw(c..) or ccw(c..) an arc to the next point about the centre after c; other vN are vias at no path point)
5V_USB: C3.1 D6.K H2.1 R3.1 U2.1 U2.3 | length 380.5
  Top Layer w8: D6.K 905.62,122.15 H2.1
  Top Layer w10: H2.1 H2.1@937.99,121.06
  Top Layer w22: H2.1 935.19,137.8 947.81,125.17 v1(947.81,101.35)
  Bottom Layer w10: U2.1 820.81,108.34 840.39,127.92 865.36,127.92 880.32,112.96 880.32,97.66 880.32,97.11
  Bottom Layer w14: U2.3 872.1,68.91 872.1,88.9 880.32,97.11 ; 880.32,97.66 881.41,98.75 916.54,98.75 C3.1@921.48,103.7
  Bottom Layer w22: C3.1@931.54,101.35 v1(947.81,101.35)
GND: C1.2 C2.2 C3.2 C4.2 C6.2 C7.2 C8.2 C9.2 C10.2 C11.2 D1.K D2.A D3.A D4.K D5.K D6.A D7.1 H1.2 H2.4 H2.5 H2.6 R1.2 TP7.1 U1.1 U1.3 U1.11 U1.20 U1.23 U1.26 U1.30 U1.38 U2.5 | length 818.3
  Top Layer w10: 312.45,186.63 315.07,186.63 ; v1(341.56,-222.52) U1.1@341.55,-196.85 ; v1@380.91,-222.44 U1.38 ; v1@668.88,-40.29 669.35,-39.82 695.42,-39.82 U1.26 ; U1.23 698.2,76.42 787.67,76.42 C6.2 ; v1@836.12,254.43 v1(836.62,254.92) ; v1(836.62,-254.92) 837.27,-254.27 837.27,-213.25 D1.K
  Top Layer w14: v1(846.5,41.93) 846.92,42.35 846.92,97.32 D6.A ; D5.K@847.34,186.02 847.34,221.57 844.5,224.41 D4.K 842.04,224.92 867.82,224.92 v1(868.32,225.42)
  Top Layer w20: C4.2 336.87,192.2 U1.11 ; U1.26@695.88,-39.37 697.67,-37.58 725.57,-37.58 ; U1.20 697.68,195.05 724.44,195.05 742.29,177.2 v1(751.36,177.2) ; 722.44,-34.45 724.13,-32.76 790,-32.76 C2.2 ; C7.2 v1@750.98,176.74 ; 751.97,-68.31 C9.2
  Bottom Layer w10: v1(237.2,55.54) 238.84,53.9 C1.2
  Bottom Layer w14: U2.5@846.4,2.97 846.4,-56.81 C8.2@846.83,-57.23
  Bottom Layer w20: 863.22,38.22 C3.2
  other v1: 400.32,-256.92 231.3,-254.92 264.76,-254.92 298.23,-254.92 333.66,-254.92 367.13,-254.92 434.06,-254.92 467.52,-254.92 500.99,-254.92 534.45,-254.92 567.92,-254.92 595.42,-255.17 634.84,-254.92 668.31,-254.92 701.77,-254.92 735.2,-254.98 768.7,-254.92 802.17,-254.92 870.08,-254.92 903.55,-254.92 937.01,-254.92 130.91,-253.94 165.35,-253.94 198.82,-253.94 98.43,-246.06 68.9,-226.38 698.76,-225 376.17,-222.42 875.47,-222.31 938.98,-219.49 310.04,-198.82 59.06,-196.85 281.5,-189.96 774.3,-187.18 736.03,-186.06 816.76,-184.94 859.78,-184.38 898.33,-183.55 934.93,-182.15 973.5,-177.98 1030.43,-174.62 255.91,-173.23 382.36,-169.04 59.06,-167.32 480,-167.28 585.62,-157.81 662.76,-154.62 1081.87,-150.89 239.17,-149.61 983.86,-137.31 198.94,-136.81 60.16,-132.87 374.99,-130.05 610,-130.6 430,-127.08 480,-126.63 519.45,-125.59 228.23,-113 1080.1,-113.19 315.6,-110.12 656.05,-106.97 60.16,-103.35 199.92,-102.36 389.15,-102.67 972.06,-101.57 430,-91.98 480,-91.54 530,-91.54 579.29,-91.24 311.14,-81.35 875.47,-81.48 227.17,-73.33 1080.1,-71.4 657.71,-68.6 441.93,-67.01 996.23,-60.82 480.31,-59.06 530.31,-59.06 60.16,-58.07 94.55,-58.07 128.94,-58.07 163.33,-58.07 197.72,-58.07 310.33,-52.17 576.28,-42.83 632.62,-42.83 669.32,-38.91 996.23,-28.92 1080.1,-29.61 305.07,-23.36 443,-20 480,-3.52 530,-3.52 576.28,-3.27 632.62,-3.27 996.23,2.97 287.48,6.14 1080.1,12.18 263.78,18.7 440.26,20.75 237.2,28.54 818.56,29.84 62.24,33.46 96.63,33.46 131.02,33.46 165.41,33.46 199.8,33.46 996.23,34.86 480,36.04 530,36.04 576.28,36.29 632.62,36.29 1080.1,50.2 996.23,66.76 440.26,70.75 480,75.6 530,75.6 576.28,75.85 632.62,75.85 60.04,77.76 670.63,77.53 199.8,78.74 1080.1,91.99 303.21,98.21 778.17,104.8 199.8,108.27 61.02,112.2 480,115.16 530,115.16 576.28,115.4 632.62,115.4 999.67,123.03 440.5,124.25 298.6,127.71 785.73,129.95 1080.1,133.78 198.82,142.72 807.09,145.5 480,154.72 530,154.72 576.28,154.96 632.62,154.96 59.06,157.48 828.17,159.16 999.37,159.19 852.82,163.78 443,165 777.09,165.56 199.8,167.32 1080.1,175.56 918.15,177.03 878.72,177.37 958.93,177.6 59.06,187.01 199.8,196.85 62.99,215.55 257.47,223.44 199.8,226.38 79.72,240.16 108.27,254.92 231.3,254.92 264.76,254.92 298.23,254.92 367.12,254.92 400.59,254.92 434.05,254.92 467.52,254.92 500.98,254.92 534.45,254.92 567.91,254.92 601.38,254.92 634.84,254.92 668.31,254.92 701.77,254.92 735.24,254.92 768.7,254.92 802.17,254.92 870.08,254.92 903.55,254.92 937.01,254.92 137.8,255.91 168.31,255.91 200.79,255.91 334.13,257.82
LED_G: R5.1 U1.19 | length 112.7
  Top Layer w8: U1.19 664.31,204.68 664.31,211.55 673.23,220.47 730.31,220.47 R5.1
LED_PWR: R13.1 U1.33 | length 218
  Top Layer w10: v1(577.78,-230.24) U1.33 ; v1(726.18,-213.2) 726.49,-212.9 747.73,-212.9 R13.1
  Mid Layer 2 w8: v1(577.78,-230.24) 580.1,-230.24 594.39,-215.96 677.59,-215.96 688.82,-204.72 717.71,-204.72 v1(726.18,-213.2)
LED_R: R4.1 U1.18 | length 156.3
  Top Layer w8: U1.18 623.03,202.77 623.03,215.55 641.73,234.25 742.13,234.25 R4.1
MM_BUSY: U1.29
MM_DBG_RX: TP6.1 U1.31 | length 93
  Top Layer w10: v1(650,-235) 656.08,-228.92 656.08,-202.32 653.54,-199.79 U1.31
  Bottom Layer w10: v1(650,-235) 650,-195 TP6.1@660,-195
MM_DBG_TX: TP5.1 U1.32 | length 85.5
  Top Layer w10: v1(611.58,-235.04) 613.43,-233.19 613.43,-200.53 U1.32
  Bottom Layer w10: TP5.1@606.58,-195.04 610,-195.04 611.58,-195.04 v1(611.58,-235.04)
MM_GPIO3: U1.21
MM_GPIO7: U1.34
MM_GPIO8: U1.35
MM_GPIO9: U1.36
MM_GPIO10: U1.37
MM_JTAG_TCK: TP1.1 U1.7 | length 77.7
  Top Layer w8: U1.7 341.64,39.49 369.52,39.49 v1(369.62,39.59)
  Bottom Layer w8: v1(369.62,39.59) 372.78,39.59 381.2,48 401.69,48 TP1.1@411.6,57.9
MM_JTAG_TDI: TP4.1 U1.9 | length 82.9
  Top Layer w8: U1.9@341.54,118.12 v1(369.09,118.11)
  Bottom Layer w8: v1(369.09,118.11) 371.33,120.35 384.35,120.35 TP4.1
MM_JTAG_TDO: TP3.1 U1.8 | length 77.5
  Top Layer w8: U1.8 v1@368.09,78.76
  Bottom Layer w8: v1(369.09,78.74) 385.77,95.42 409.42,95.42 TP3.1
MM_JTAG_TMS: TP2.1 U1.6 | length 72.6
  Top Layer w8: U1.6 v1@368.09,0.02
  Bottom Layer w8: v1(369.28,0.54) 369.55,0.27 404.27,0.27 TP2.1@412,8
MM_RESET_N: C1.1 R7.1 U1.4 | length 276.4
  Top Layer w8: U1.4 v1(369.09,-78.74)
  Mid Layer 2 w8: v1(295.51,66.43) 295.51,42.87 341.56,-3.17 341.56,-51.2 v1(369.09,-78.74)
  Bottom Layer w8: R7.1 264.76,88.88 C1.1 285.78,87.9 293.28,80.4 293.28,68.66 v1(295.51,66.43)
MM_SD_CLK: U1.17
MM_SD_CMD: U1.16
MM_SD_D0: U1.12
MM_SD_D1: U1.14
MM_SD_D2: U1.15
MM_SD_D3: U1.13
MM_WAKE: S1.1 U1.5 | length 346.2
  Top Layer w8: U1.5 v1@367.11,-39.35
  Mid Layer 2 w8: v1(369.62,-39.35) 537.38,-39.35 556.85,-58.82 v1(556.85,-127.85)
  Bottom Layer w8: S1.1 556.85,-170.08 v1(556.85,-127.85)
NetC5_2: C5.2 R1.1 R2.2 U2.6 | length 119.9
  Bottom Layer w8: R2.2 C5.2 ; R1.1 R1.1@794.71,-26.72 ; C5.2@794.71,-71.84 C5.2@795.84,-72.97 ; C5.2@794.71,-65.94 R1.1@794.71,-27.34 ; R1.1@795.22,-27.86 R1.1@794.71,-27.34 ; U2.6 820.81,-4.03 817.92,-6.92 814.89,-6.92 795.09,-26.72 R1.1@794.71,-26.72 ; R1.1@794.71,-27.34 R1.1@794.71,-26.72
NetD1_A: D1.A R13.2 | length 34.8
  Top Layer w8: R13.2 D1.A
NetD4_A: D4.A R4.2 | length 40
  Top Layer w8: R4.2 769.62,226.44 804.07,226.44 D4.A
NetD5_A: D5.A R5.2 | length 45.4
  Top Layer w8: R5.2 785.62,202.76 796.32,192.05 796.32,191.87 802.17,186.02 D5.A
NetD7_2: D7.2 H1.1 U1.2 | length 382
  Top Layer w17.87: H1.1 209.91,-10.83 cw(c209.91,-70.6) 269.69,-70.6 269.81,-70.72 269.81,-108.24 ; 269.81,-110.57 269.81,-108.24 ; U1.2 322.55,-157.46 cw(c322.55,-104.6) 269.81,-108.24
NetL1_1: L1.1 U2.4
NetR3_2: R3.2 U2.2 | length 40.5
  Bottom Layer w8: U2.2 846.4,100.79 R3.2
USB_D_N: D3.K H2.2 U1.27 | length 309.2
  Top Layer w9.45: U1.27 707.96,-90.81 751.97,-90.81 785.59,-90.81 ccw(c785.59,-52.33) 812.79,-79.56 817.14,-75.2 ; 817.16,-75.19 ccw(c795.14,-53.2) 826.26,-53.2 826.26,-21.49 cw(c857.78,-21.49) 832.35,-2.86 832.98,-2.23 cw(c856.7,-25.95) 856.7,7.6 861.51,7.6 ccw(c861.51,31.93) 878.72,14.72 890.7,26.71 cw(c921.26,-3.84) H2.2
USB_D_P: D2.K H2.3 U1.28 | length 310.5
  Top Layer w9.45: U1.28 707.96,-106.01 751.97,-106.01 785.59,-106.01 ccw(c785.59,-52.33) 823.55,-90.29 832.34,-81.5 ; 832.35,-81.48 ccw(c810.34,-59.49) 841.45,-59.49 841.45,-19.76 cw(c853.62,-19.76) 845.01,-11.16 cw(c853.62,-19.76) 853.62,-7.6 861.51,-7.6 cw(c861.51,-31.93) 878.72,-14.72 890.7,-26.71 ccw(c921.26,3.84) H2.3
VDD_3V3: C2.1 C4.1 C5.1 C6.1 C7.1 C8.1 C9.1 C10.1 C11.1 L1.2 R2.1 R7.2 S1.2 TP8.1 U1.10 U1.22 U1.24 U1.25 | length 1880.4
  Top Layer w22: U1.25 696.68,0.83 C9.1@751.97,0.83 ; U1.24 696.57,40.09 C11.1 C6.1 ; U1.22 696.57,118.83 C7.1 ; C9.1 C2.1
  Top Layer w25: C4.1 237.71,157.5 C10.1@277.37,157.5 ; C10.1@277.16,157.28 C10.1@277.37,157.5 ; U1.10 C10.1@277.37,157.5
  Mid Layer 2 w10: v1(403.62,-232.45) 447.09,-188.98 661.01,-188.98 723.41,-126.58
  Mid Layer 2 w38: v1(262.2,157.28) 262.2,173.5 309.18,220.47 621.46,220.47 v1(724.04,117.89) ; 723.41,-26.24 723.41,-126.58 745.67,-148.84 v1(811.41,-148.84) ; 723.4,-25.01 v1@723.4,38.76 ; v1(724.24,38.76) v1@724.24,117.69
  Bottom Layer w8: v1(262.2,157.28) 263.48,156 263.48,134.74 264.48,133.74 R7.2@265.67,133.74 ; v1(403.62,-232.45) 403.62,-231.83 413.07,-222.37 S1.2
  Bottom Layer w10: R2.1 C5.1
  Bottom Layer w22: v1(262.2,157.28) v1@262.4,157.48
  Bottom Layer w30: v1@262.4,157.48 296.46,157.48 336.98,198 TP8.1
  other v1: 785.3,-148.7 724.64,0.59
pads on no net: H2.

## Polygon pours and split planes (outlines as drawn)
GND on Bottom Layer "GND_L04_P014" (solid, remove dead copper, pour order 14): 39.37,-275.59 1118.11,-275.59 1118.11,275.59 39.37,275.59
NetL1_1 on Bottom Layer "NONET_L-01_P-001" (solid, pour order 7): 881.28,10.72 912.51,10.72 938.98,-15.75 938.98,-38.31 895.64,-38.31 868.05,-10.72 868.05,10.72
VDD_3V3 on Bottom Layer "NONET_L-01_P-001" (solid, pour order 11): 846.26,-98.4 948.85,-98.4 948.85,-141.7 948.82,-141.73 924.42,-141.73 905.05,-161.1 775.28,-161.1 768.7,-154.52 768.7,-128.94 786.11,-111.53 786.11,-98.66
GND on Mid Layer 1 "GND_L02_P001" (solid, remove dead copper, pour order 1): 39.37,-275.59 1116.14,-275.59 1116.14,275.59 39.37,275.59
GND on Mid Layer 2 "GND_L03_P009" (solid, remove dead copper, pour order 9): 39.37,-275.59 1114.17,-275.59 1114.17,275.59 39.37,275.59
GND on Top Layer "GND_L01_P008" (solid, remove dead copper, pour order 8): 39.37,-275.59 1113.19,-275.59 1113.19,275.59 39.37,275.59

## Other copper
Top Layer:
  rectangle net NetD7_2: 45.87,-19.76 120.11,-1.89
  text ".Layer_Name" at 414.48,-359.75 h60
Mid Layer 2:
  text ".Layer_Name" at 413.19,-359.75 h60
Mid Layer 1:
  text ".Layer_Name" at 416.69,-359.75 h60
Bottom Layer:
  text ".Layer_Name" at 377.04,-359.75 h60

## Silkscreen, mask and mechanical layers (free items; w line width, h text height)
Top Overlay:
  circle w10: c847.17,146.33 r1.63
  text "v5" at 62.38,158.3 h60
  text "USB" at 750.43,-198.96 h47.24
  text "RD09" at 72.44,-249.66 h74.8
  text ".Layer_Name" at 389.75,-359.75 h60
Bottom Overlay:
  text "3V3" at 374.91,187.13 h39.37
  text "TDI" at 374.91,137.17 h39.37
  text "TDO" at 374.91,86.64 h39.37
  text "TCK" at 374.91,35.89 h39.37
  text "TMS" at 374.91,-12.58 h39.37
  text "GND" at 374.91,-64.75 h39.37
  text "TX" at 615.91,-251.06 h39.37
  text "RX" at 687.74,-251.06 h39.37
  text "RD09 v5" at 385.16,-255.12 h78.74
  text "WAKE" at 542.86,-267.76 h39.37
  text ".Layer_Name" at 352.31,-359.75 h60
Top Paste:
  text ".Layer_Name" at 414.46,-360.39 h60
Bottom Paste:
  text ".Layer_Name" at 377.02,-370.44 h60
Top Solder:
  text ".Layer_Name" at 404.04,-360.39 h60
Bottom Solder:
  text ".Layer_Name" at 366.59,-370.44 h60
Drill Guide:
  text ".Layer_Name" at 412.96,-370.44 h60
Fab Notes:
  lines w3.94: -343.36,-884.02 -343.36,-432.28 1193.7,-432.28 1193.7,-884.48 -342.91,-884.48 ; 190.1,-883.08 190.1,-432.28 ; 190.1,-794.02 1195.02,-794.02 ; 190.1,-703.93 1195.02,-703.93 ; 190.1,-613.38 1195.02,-613.38 ; 190.1,-522.83 1195.02,-522.83 ; 897.78,-885.46 897.78,-794.91
  text "NOTES: UNLESS OTHERWISE SPECIFIED0" at -3003.94,3069.93 h60
  text "1. SPECIFICATIONS/TOLERANCES:" at -3003.94,2999.93 h60
  text "A. FABRICATE PER IPC-6012, CLASS 2, USING PROVIDED DATA FILES XXXXXXXX.ZIP" at -3003.94,2929.93 h60
  text "B. ALL SPECIFICATIONS USED SHALL BE PER THEIR LATEST REVISIONS." at -3003.94,2859.93 h60
  text "C. THE DIMENSIONS OF CIRCUIT FEATURES IN THE PROVIDED DATA MAY BE ADJUSTED" at -3003.94,2789.93 h60
  text "ONLY TO COMPENSATE FOR PROCESS TOLERANCES; ADDING, REMOVING OR RELOCATING" at -3003.94,2719.93 h60
  text "CIRCUIT FEATURES IS NOT ALLOWED" at -3003.94,2649.93 h60
  text "D. REMOVE ALL BURRS AND BREAK SHARP EDGES, .381 [.015] MAX RADIUS." at -3003.94,2579.93 h60
  text "E. PARENTHETICAL INFORMATION IS FOR REFERENCE ONLY." at -3003.94,2509.93 h60
  text "F. REPAIR OF PCB DEFECTS IS NOT PERMITTED." at -3003.94,2439.93 h60
  text "2. DIELECTRIC MATERIAL:" at -3003.98,2299.93 h60
  text "A. DIELECTRIC MATERIAL SHALL BE PER IPC-4101/99, /124, /126 OR /129 (RoHS COMPLIANT EPOXY-GLASS)" at -3003.94,2229.93 h60
  text "B. MINIMUM DIELECTRIC THICKNESS SHALL BE .051 [.002] FOR REFERENCED STACK-UP" at -3003.94,2159.93 h60
  text "DIMENSIONS OF.076 [.003] OR GREATER; IPC-6012 REQUIREMENTS SHALL OTHERWISE" at -3003.94,2089.93 h60
  text "APPLY. SINGLE-PLY CONSTRUCTION IS ALLOWED." at -3003.94,2019.93 h60
  text "C. SEE LAYER STACK-UP FOR REQUIRED COPPER WEIGHTS AND THE FINISHED PCB" at -3003.94,1949.93 h60
  text "THICKNESS. IF SPECIFIED, 1/3 OZ. STARTING FOIL MAY BE ACHIEVED BY 1/2 OZ. FOIL REDUCTION." at -3003.94,1879.93 h60
  text "D. FINISHED PCB THICKNESS SHALL BE MEASURED OVER LANDS AND/OR" at -3003.94,1809.93 h60
  text "CONDUCTORS NOT COVERED BY SOLDER MASK. IF SPECIFIED, 1/3 OZ. STARTING FOIL" at -3003.94,1739.93 h60
  text "MAY BE ACHIEVED BY 1/2 OZ. FOIL REDUCTION." at -3003.94,1669.93 h60
  text "3. DRILLING:" at -3003.94,1529.93 h60
  text "A. VIA DIAMETERS SHALL BE VERIFIED BEFORE PLATING; ALL OTHER HOLE" at -3003.94,1459.93 h60
  text "DIAMETERS ARE FINISHED DIMENSIONS." at -3003.94,1389.93 h60
  text "B. LAYER-TO-LAYER MISREGISTRATION SHALL BE .127 [.005] MAXIMUM." at -3003.94,1319.93 h60
  text "4. SOLDER MASK:" at -3003.94,1179.93 h60
  text "A. APPLY LPI SOLDER MASK OVER BARE COPPER USING PROVIDED DATA." at -3003.94,1109.93 h60
  text "B. SOLDER MASK SHALL BE PER IPC-SM-840, CLASS T, COLOR PURPLE." at -3003.94,1039.93 h60
  text "C. THE DIMENSIONS OF SOLDER MASK-DEFINED PADS ON PLANES AND/OR WIDE" at -3003.94,969.93 h60
  text "CONDUCTORS SHALL NOT BE MODIFIED." at -3003.94,899.93 h60
  text "5. SILKSCREEN/MARKING:" at -3003.94,759.93 h60
  text "A. SILKSCREEN PCB PER PROVIDED DATA USING PERMANENT, NON-CONDUCTIVE" at -3003.94,689.93 h60
  text "INK, COLOR WHITE." at -3003.94,619.93 h60
  text "B. SUPPLIER ID AND TRACEABILITY INFORMATION SHALL NOT / BE APPLIED ON ANY PART OF THE PCB" at -3002.91,446.18 h60
  text "C. INK SHALL NOT BE APPLIED TO ANY SOLDERABLE SURFACE." at -3003.94,370.56 h60
  text "USING PROVIDED DATA." at -3003.94,300.56 h60
  text "6. ELECTRICAL TEST:" at -3003.94,160.56 h60
  text "A. DESIGN VERIFICATION SHALL BE DONE PRIOR TO PCB FABRICATION USING" at -3003.94,90.56 h60
  text "GERBER DATA AND AN IPC-D-356 NETLIST." at -3003.94,20.56 h60
  text "B. ALL PCBS SHALL BE 100% ELECTRICALLY TESTED FOR OPENS AND SHORTS" at -3003.94,-49.44 h60
  text "C. APPLY TEST STAMP IN NON-LEGEND AREA ON SECONDARY SIDE OF PCB." at -3003.94,-119.44 h60
  text "7. FINAL FINISH:" at -3003.94,-254.44 h60
  text "A. FINAL FINISH SHALL BE ELECTROLESS NICKEL/IMMERSION GOLD (ENIG) PER IPC-4552." at -3003.94,-328.47 h60
  text "8. IMPEDANCE:" at -3007.4,-436.55 h60
  text "Project:" at 207.82,-495.27 h60
  text "RD09" at 468.65,-500.19 h80
  text "A. IMPEDANCE TOLERANCE SHALL BE +/- 10%." at -3007.4,-506.55 h60
  text "B. SEE LAYER STACK-UP FOR IMPEDANCE REQUIREMENTS." at -3007.4,-576.55 h60
  text "Company:" at 207.82,-585.82 h60
  text "Morse Micro" at 468.7,-590.74 h80
  text "Drawn By:" at 207.82,-676.37 h60
  text ".DrawnBy" at 468.65,-683.26 h80
  text "9. IF PANELIZATION SPECIFICATIONS ARE PROVIDED, THE PCBS SHALL BE DELIVERED IN PANEL" at -2993.94,-699.44 h60
  text "FORM. HOWEVER, THESE SPECIFICATIONS MAY BE REPLACED BY SUPPLIER PREFERRED" at -2993.94,-769.44 h60
  text "(SPECIFICATIONS AS APPROVED)." at -2993.94,-839.44 h60
  text "Date:" at 207.82,-856.92 h60
  text "Rev:" at 926.32,-860.86 h60
  text ".Print_Date" at 468.65,-867.75 h80
  text ".Revision" at 1054.28,-867.75 h80
Board:
  the board outline again, w3.94
Drill Drawing:
  text ".Layer_Name" at 386.83,-359.75 h60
